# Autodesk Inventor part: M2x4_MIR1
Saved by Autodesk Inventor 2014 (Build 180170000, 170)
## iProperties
Created: 2015-05
Part Number: M2x4_MIR1
Material: 일반
Vendor: CBT Solutions
Document SubType Name: 모델링
Designer: Administrator
Appearance: 기본값
Company: 한국ATC센터
Author: KYOUNG IL JANG
Comments: 파생
d0: 1.000 ul
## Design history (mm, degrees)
derived "M2x4.ipt" dims count "d0" = 1
feature "솔리드1::M2x4.ipt" dims count "d0" = 1
tag "피쳐 태그1"
node "솔리드1"
